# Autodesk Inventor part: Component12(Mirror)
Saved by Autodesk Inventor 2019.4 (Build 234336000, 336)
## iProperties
Created: 2020-06
Part Number: Component12(Mirror)
Material: Generic
Document SubType Name: Modeling
Designer: Administrator
Density: 1 g/cm^3
Appearance: Default
Title: Component12(Mirror)
Author: Administrator
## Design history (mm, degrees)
